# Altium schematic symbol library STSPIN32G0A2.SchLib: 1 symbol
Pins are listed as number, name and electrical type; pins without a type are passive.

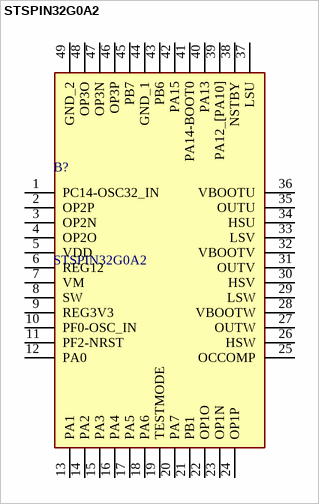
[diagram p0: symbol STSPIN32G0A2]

## STSPIN32G0A2
designator B?
Advanced brushless motor controller with embedded STM32G0 MCU Operating voltage from 6.7 to 45 V temperature range: -40 to +125 C; Manufacturer_Name: STMicroelectronics; Geometry.Height: 1.05mm
footprint QFN50P700X700X105-49N-D
pins: 1 PC14-OSC32_IN, 2 OP2P, 3 OP2N, 4 OP2O, 5 VDD, 6 REG12, 7 VM, 8 SW, 9 REG3V3, 10 PF0-OSC_IN, 11 PF2-NRST, 12 PA0, 13 PA1, 14 PA2, 15 PA3, 16 PA4, 17 PA5, 18 PA6, 19 TESTMODE, 20 PA7, 21 PB1, 22 OP1O, 23 OP1N, 24 OP1P, 25 OCCOMP, 26 HSW, 27 OUTW, 28 VBOOTW, 29 LSW, 30 HSV, 31 OUTV, 32 VBOOTV, 33 LSV, 34 HSU, 35 OUTU, 36 VBOOTU, 37 LSU, 38 NSTBY, 39 PA12_[PA10], 40 PA13, 41 PA14-BOOT0, 42 PA15, 43 PB6, 44 GND_1, 45 PB7, 46 OP3P, 47 OP3N, 48 OP3O, 49 GND_2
